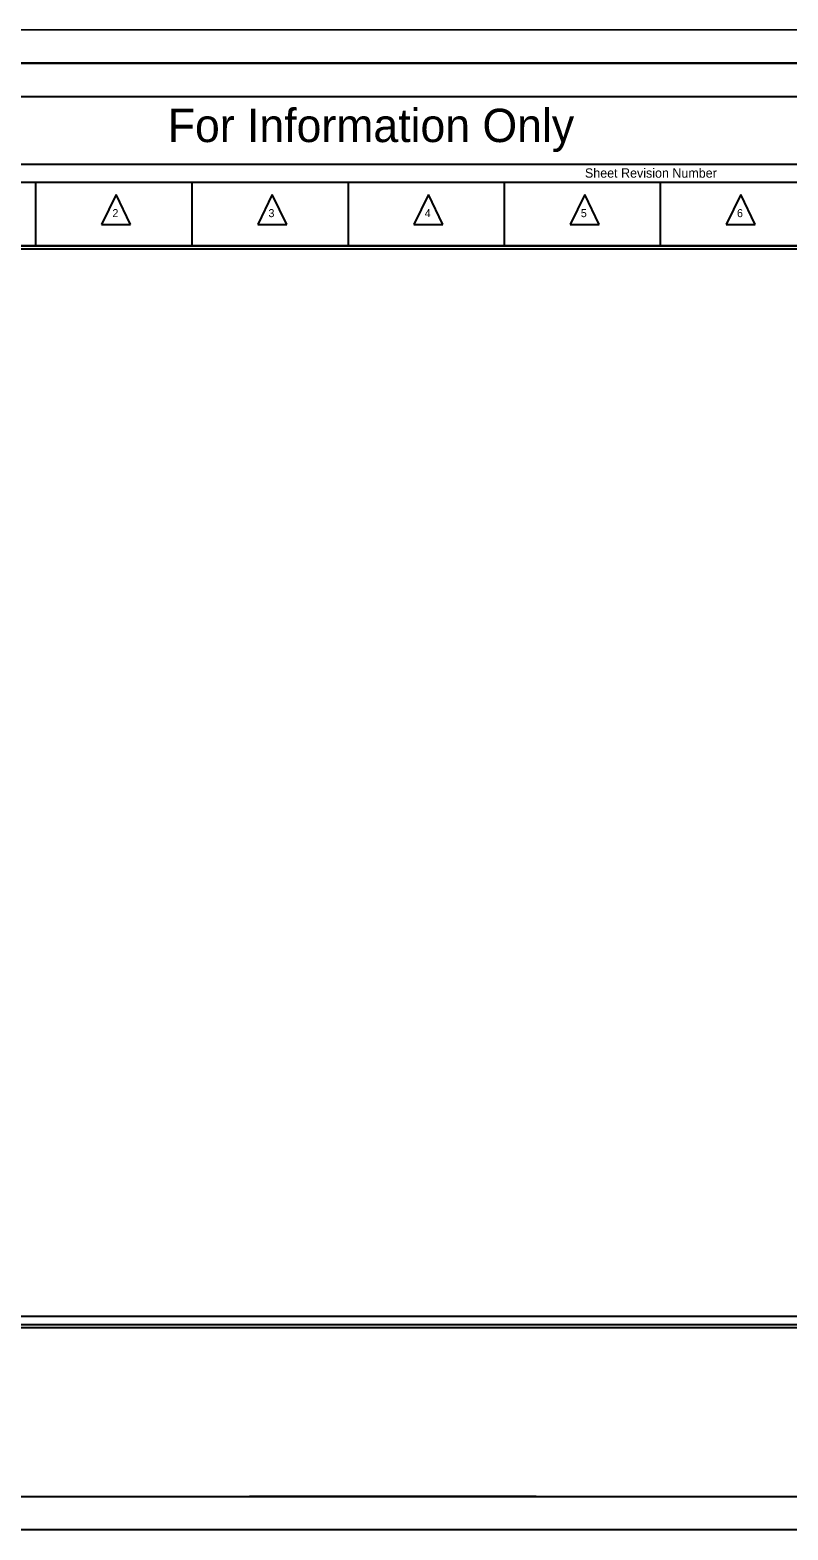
# Model space of a CAD drawing. Extents: x -2251 to 10196, y -13470 to 1199.
# Drawn here: x 8172 to 8740, y -2926 to -1801 of the extents above; entities that cross this region are included whole.
import ezdxf

# ---------------------------------------------------------------- set-up
doc = ezdxf.new("R2010")
doc.units = 0
for name, color, linetype in [('RD_SHT_Bndy', 7, 'Continuous'), ('RD_SHT_Iplotshp', 7, 'Continuous'), ('RD_SHT_Snap', 7, 'Continuous'), ('RD_SHT_TX', 7, 'Continuous'), ('RD_TX_RoadID', 7, 'Continuous')]:
    doc.layers.add(name, color=color, linetype=linetype)

msp = doc.modelspace()

# ---------------------------------------------------------------- linework, layer by layer
at = {"layer": 'RD_SHT_Bndy'}
for p, q in [((9291.6, -1800.7), (7531.6, -1800.6)), ((9291.6, -1825.6), (7531.6, -1825.6)), ((7603.1, -1850.6), (9278.1, -1850.6)), ((7653.4, -1914.8), (9231.1, -1914.8)), ((8176, -1962.6), (8176, -1914.8)), ((8293.1, -1962.6), (8293.1, -1914.8)), ((8410.2, -1962.6), (8410.2, -1914.8)), ((8527.3, -1962.6), (8527.3, -1914.8)), ((8644.3, -1962.6), (8644.3, -1914.8)), ((8236.2, -1924.1), (8225.2, -1946.6)), ((8246.9, -1946.6), (8236.2, -1924.1)), ((8353.2, -1924.1), (8342.3, -1946.6)), ((8364, -1946.6), (8353.2, -1924.1)), ((8470.3, -1924.1), (8459.4, -1946.6)), ((8481.1, -1946.6), (8470.3, -1924.1)), ((8587.4, -1924.1), (8576.5, -1946.6)), ((8598.2, -1946.6), (8587.4, -1924.1)), ((8704.5, -1924.1), (8693.5, -1946.6)), ((8715.3, -1946.6), (8704.5, -1924.1)), ((8225.2, -1946.6), (8246.9, -1946.6)), ((8342.3, -1946.6), (8364, -1946.6)), ((8459.4, -1946.6), (8481.1, -1946.6)), ((8576.5, -1946.6), (8598.2, -1946.6)), ((8693.5, -1946.6), (8715.3, -1946.6)), ((7653.4, -1962.6), (9231.1, -1962.6)), ((7603.1, -2900.6), (9278.1, -2900.6)), ((8550.9, -2900.6), (8336.1, -2900.6)), ((9291.6, -2925.6), (7531.6, -2925.6))]:
    msp.add_line(p, q, dxfattribs=at)
msp.add_lwpolyline([(7653.4, -1901.3), (9231.1, -1901.3), (9231.1, -2765.6), (7653.4, -2765.6)], close=True, dxfattribs=at)
at = {"layer": 'RD_SHT_Iplotshp'}
msp.add_lwpolyline([(7496.6, -1825.6), (9296.6, -1825.6), (9296.6, -2925.6), (7496.6, -2925.6)], close=True, dxfattribs=at)
at = {"layer": 'RD_SHT_Snap'}
msp.add_lwpolyline([(7508.1, -1825.6), (9308.1, -1825.6), (9308.1, -2925.6), (7508.1, -2925.6)], close=True, dxfattribs=at)
at = {"layer": 'RD_TX_RoadID'}
for points in [[(7647.4, -2771.4), (9237.1, -2771.4), (9237.1, -1965), (7647.4, -1965)], [(7653.4, -2773.8), (9231.1, -2773.8), (9231.1, -1962.6), (7653.4, -1962.6)]]:
    msp.add_lwpolyline(points, close=True, dxfattribs=at)

# ---------------------------------------------------------------- texts
at = {"layer": 'RD_SHT_Bndy'}
for s, height, p in [('Sheet Revision Number', 7, (8587.6, -1911.4)), ('2', 6, (8233.3, -1941)), ('3', 6, (8350.3, -1941)), ('4', 6, (8467.5, -1941)), ('5', 6, (8584.5, -1941)), ('6', 6, (8701.6, -1941))]:
    msp.add_text(s, height=height, dxfattribs=at).set_placement(p)
at = {"layer": 'RD_SHT_TX'}
msp.add_text('For Information Only', height=25, dxfattribs=at).set_placement((8274.8, -1884.7))

doc.saveas('drawing.dxf')
